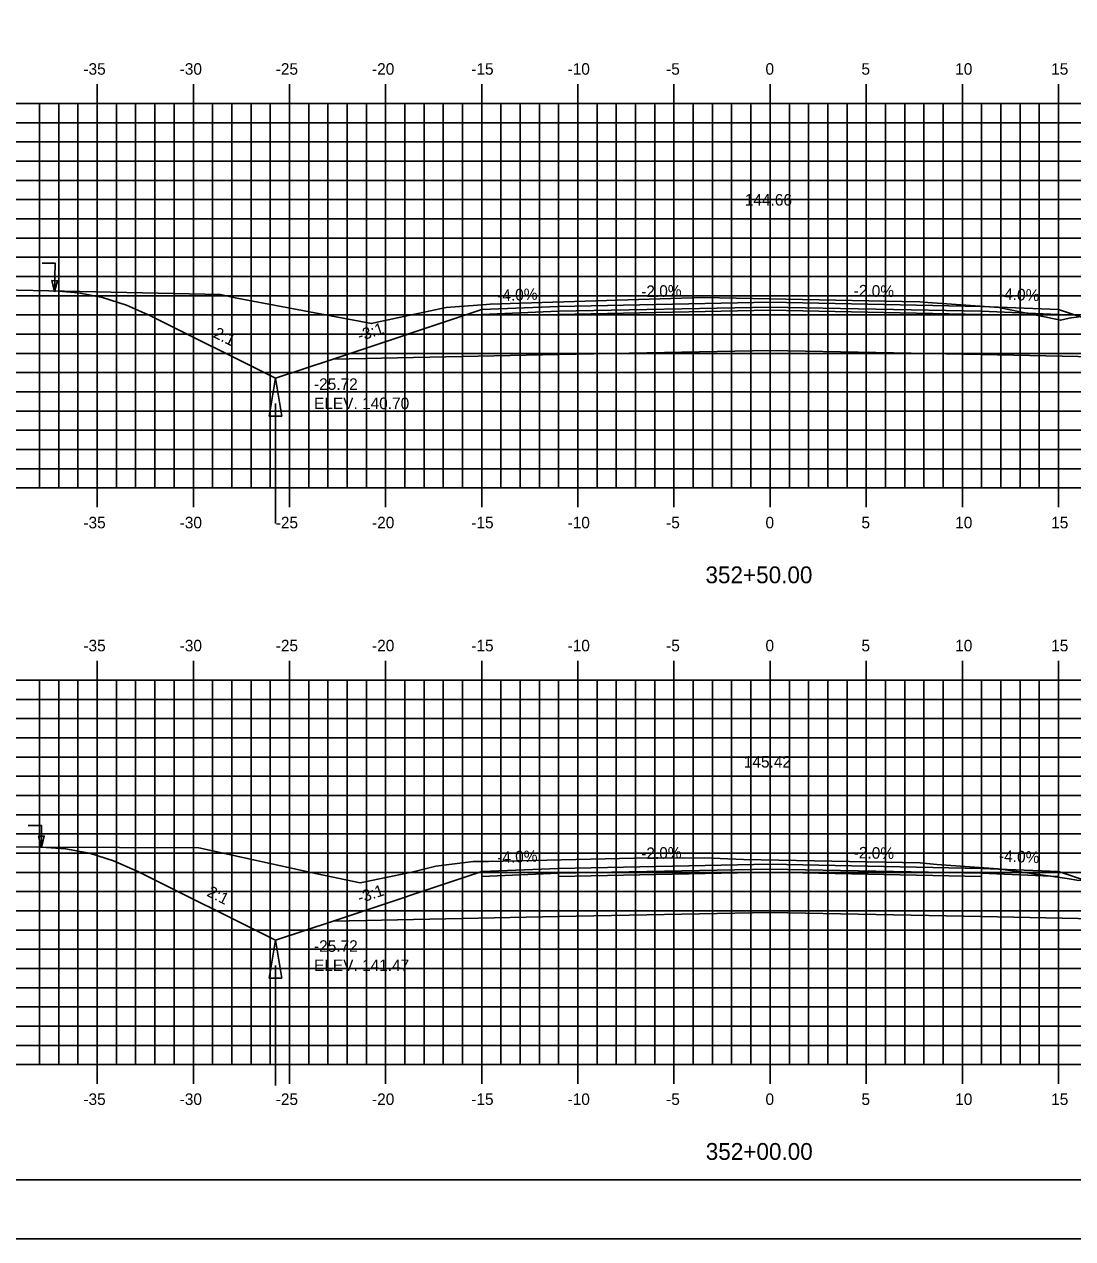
# Model space of a CAD drawing. Extents: x 1144972 to 1145142, y 608981 to 609091.
# Drawn here: x 1145016.6 to 1145071.1, y 608981.3 to 609044.5 of the extents above; entities that cross this region are included whole.
import ezdxf

# ---------------------------------------------------------------- set-up
doc = ezdxf.new("R2010")
doc.units = 0
for name, color, linetype in [('ANNOTATION', 7, 'Continuous'), ('BORDER', 7, 'Continuous'), ('D_Drainage_Ditch_Line', 7, 'Continuous'), ('D_Roadway_Centerline', 7, 'Continuous'), ('D_Roadway_Centerline_Text', 7, 'Continuous'), ('D_Roadway_Edge_Shoulder', 7, 'Continuous'), ('D_Roadway_Edge_TW', 7, 'Continuous'), ('D_Roadway_Pavement', 7, 'Continuous'), ('D_Roadway_SlopeLines', 7, 'Continuous'), ('D_Roadway_SubGrade', 7, 'Continuous'), ('D_Text_Standard', 7, 'Continuous'), ('H_V ANNOTATION', 7, 'Continuous'), ('MAJOR', 7, 'Continuous'), ('MINOR', 7, 'Continuous'), ('PLOT BOUNDARY', 7, 'Continuous'), ('S_Roadway_Centerline', 7, 'Continuous')]:
    doc.layers.add(name, color=color, linetype=linetype)

msp = doc.modelspace()

# ---------------------------------------------------------------- linework, layer by layer
for points in [[(1145018.151, 609030.592), (1145019.401, 609030.491), (1145020.651, 609030.24), (1145021.901, 609029.839), (1145023.151, 609029.289), (1145029.651, 609026.039), (1145032.651, 609027.039), (1145040.374, 609029.614), (1145040.375, 609029.614), (1145044.375, 609029.774), (1145055.375, 609029.994), (1145066.375, 609029.774), (1145070.375, 609029.614), (1145078.099, 609027.039), (1145081.099, 609026.039), (1145086.528, 609028.754), (1145087.778, 609029.302), (1145089.028, 609029.695), (1145090.278, 609029.934), (1145091.528, 609030.018)], [(1145017.48, 609001.649), (1145018.73, 609001.566), (1145019.98, 609001.328), (1145021.23, 609000.935), (1145022.48, 609000.387), (1145029.651, 608996.802), (1145032.651, 608997.802), (1145040.374, 609000.376), (1145040.375, 609000.376), (1145044.375, 609000.536), (1145055.375, 609000.756), (1145066.375, 609000.536), (1145070.375, 609000.376), (1145078.099, 608997.802), (1145081.099, 608996.802), (1145084.992, 608998.748), (1145086.242, 608999.29), (1145087.492, 608999.664), (1145088.742, 608999.87), (1145089.992, 608999.91)]]:
    msp.add_lwpolyline(points)
at = {"layer": 'BORDER'}
msp.add_lwpolyline([(1144980.376, 608984.335), (1145140.376, 608984.335), (1145140.376, 609089.335), (1144980.376, 609089.335)], close=True, dxfattribs=at)
at = {"layer": 'D_Drainage_Ditch_Line'}
for p, q in [((1145029.651, 609024.727), (1145029.65, 609018.483)), ((1145029.651, 608995.489), (1145029.65, 608989.246))]:
    msp.add_line(p, q, dxfattribs=at)
for points in [[(1145029.979, 609024.071), (1145029.323, 609024.071), (1145029.651, 609026.039)], [(1145029.979, 608994.833), (1145029.323, 608994.833), (1145029.651, 608996.802)]]:
    msp.add_lwpolyline(points, close=True, dxfattribs=at)
at = {"layer": 'D_Roadway_Edge_Shoulder'}
for points in [[(1145044.375, 609029.774), (1145040.375, 609029.614), (1145040.375, 609029.364), (1145044.375, 609029.524)], [(1145066.375, 609029.774), (1145070.375, 609029.614), (1145070.375, 609029.364), (1145066.375, 609029.524)], [(1145044.375, 609000.536), (1145040.375, 609000.376), (1145040.375, 609000.126), (1145044.375, 609000.286)], [(1145066.375, 609000.536), (1145070.375, 609000.376), (1145070.375, 609000.126), (1145066.375, 609000.286)]]:
    msp.add_lwpolyline(points, close=True, dxfattribs=at)
at = {"layer": 'D_Roadway_Edge_TW'}
for points in [[(1145044.375, 609029.524), (1145044.375, 609029.774), (1145055.375, 609029.994), (1145066.375, 609029.774), (1145066.375, 609029.524), (1145055.375, 609029.744)], [(1145044.375, 609000.286), (1145044.375, 609000.536), (1145055.375, 609000.756), (1145066.375, 609000.536), (1145066.375, 609000.286), (1145055.375, 609000.506)]]:
    msp.add_lwpolyline(points, close=True, dxfattribs=at)
at = {"layer": 'D_Roadway_Pavement'}
for points in [[(1145044.375, 609029.357), (1145044.375, 609029.524), (1145055.375, 609029.744), (1145066.375, 609029.524), (1145066.375, 609029.357), (1145055.375, 609029.577)], [(1145044.375, 609000.119), (1145044.375, 609000.286), (1145055.375, 609000.506), (1145066.375, 609000.286), (1145066.375, 609000.119), (1145055.375, 609000.339)]]:
    msp.add_lwpolyline(points, close=True, dxfattribs=at)
at = {"layer": 'D_Roadway_SlopeLines'}
for points in [[(1145029.651, 609026.039), (1145023.151, 609029.289), (1145021.901, 609029.839), (1145020.651, 609030.24), (1145019.401, 609030.491), (1145018.151, 609030.592)], [(1145032.651, 609027.039), (1145029.651, 609026.039)], [(1145029.651, 608996.802), (1145022.48, 609000.387), (1145021.23, 609000.935), (1145019.98, 609001.328), (1145018.73, 609001.566), (1145017.48, 609001.649)], [(1145032.651, 608997.802), (1145029.651, 608996.802)]]:
    msp.add_lwpolyline(points, dxfattribs=at)
at = {"layer": 'D_Roadway_SubGrade'}
for points in [[(1145044.375, 609029.357), (1145044.375, 609029.524), (1145040.375, 609029.364), (1145040.375, 609029.614), (1145040.374, 609029.614), (1145032.651, 609027.039), (1145044.375, 609027.274)], [(1145044.375, 609027.274), (1145044.375, 609029.357), (1145055.375, 609029.577), (1145066.375, 609029.357), (1145066.375, 609027.274), (1145055.375, 609027.494)], [(1145066.375, 609029.357), (1145066.375, 609029.524), (1145070.375, 609029.364), (1145070.375, 609029.614), (1145070.376, 609029.614), (1145078.099, 609027.039), (1145066.375, 609027.274)], [(1145044.375, 609000.119), (1145044.375, 609000.286), (1145040.375, 609000.126), (1145040.375, 609000.376), (1145040.374, 609000.376), (1145032.651, 608997.802), (1145044.375, 608998.036)], [(1145044.375, 608998.036), (1145044.375, 609000.119), (1145055.375, 609000.339), (1145066.375, 609000.119), (1145066.375, 608998.036), (1145055.375, 608998.256)], [(1145066.375, 609000.119), (1145066.375, 609000.286), (1145070.375, 609000.126), (1145070.375, 609000.376), (1145070.376, 609000.376), (1145078.099, 608997.802), (1145066.375, 608998.036)]]:
    msp.add_lwpolyline(points, close=True, dxfattribs=at)
at = {"layer": 'D_Text_Standard'}
for points in [[(1145018.151, 609030.539), (1145018.185, 609032.037), (1145017.505, 609032.037)], [(1145017.48, 609001.637), (1145017.469, 609002.782), (1145016.789, 609002.782)]]:
    msp.add_lwpolyline(points, dxfattribs=at)
for points in [[(1145018.151, 609030.539), (1145018.019, 609031.124), (1145018.31, 609031.117)], [(1145017.48, 609001.637), (1145017.329, 609002.218), (1145017.62, 609002.22)]]:
    msp.add_lwpolyline(points, close=True, dxfattribs=at)
at = {"layer": 'MAJOR'}
for p, q in [((1145020.375, 609041.337), (1145020.375, 609040.335)), ((1145025.375, 609041.337), (1145025.375, 609040.335)), ((1145030.375, 609041.337), (1145030.375, 609040.335)), ((1145035.375, 609041.337), (1145035.375, 609040.335)), ((1145040.375, 609041.337), (1145040.375, 609040.335)), ((1145045.375, 609041.337), (1145045.375, 609040.335)), ((1145050.375, 609041.337), (1145050.375, 609040.335)), ((1145055.375, 609041.337), (1145055.375, 609040.335)), ((1145060.375, 609041.337), (1145060.375, 609040.335)), ((1145065.375, 609041.337), (1145065.375, 609040.335)), ((1145070.375, 609041.337), (1145070.375, 609040.335)), ((1144985.375, 609040.335), (1145125.375, 609040.335)), ((1144985.375, 609040.335), (1145125.375, 609040.335)), ((1145020.375, 609020.335), (1145020.375, 609040.335)), ((1145025.375, 609020.335), (1145025.375, 609040.335)), ((1145030.375, 609020.335), (1145030.375, 609040.335)), ((1145035.375, 609020.335), (1145035.375, 609040.335)), ((1145040.375, 609020.335), (1145040.375, 609040.335)), ((1145045.375, 609020.335), (1145045.375, 609040.335)), ((1145050.375, 609020.335), (1145050.375, 609040.335)), ((1145055.375, 609020.335), (1145055.375, 609040.335)), ((1145060.375, 609020.335), (1145060.375, 609040.335)), ((1145065.375, 609020.335), (1145065.375, 609040.335)), ((1145070.375, 609020.335), (1145070.375, 609040.335)), ((1144985.375, 609035.335), (1145125.375, 609035.335)), ((1144985.375, 609030.335), (1145125.375, 609030.335)), ((1144985.375, 609025.335), (1145125.375, 609025.335)), ((1144985.375, 609020.335), (1145125.375, 609020.335)), ((1144985.375, 609020.335), (1145125.375, 609020.335)), ((1145020.375, 609019.333), (1145020.375, 609020.335)), ((1145025.375, 609019.333), (1145025.375, 609020.335)), ((1145030.375, 609019.333), (1145030.375, 609020.335)), ((1145035.375, 609019.333), (1145035.375, 609020.335)), ((1145040.375, 609019.333), (1145040.375, 609020.335)), ((1145045.375, 609019.333), (1145045.375, 609020.335)), ((1145050.375, 609019.333), (1145050.375, 609020.335)), ((1145055.375, 609019.333), (1145055.375, 609020.335)), ((1145060.375, 609019.333), (1145060.375, 609020.335)), ((1145065.375, 609019.333), (1145065.375, 609020.335)), ((1145070.375, 609019.333), (1145070.375, 609020.335)), ((1145020.375, 609011.337), (1145020.375, 609010.335)), ((1145025.375, 609011.337), (1145025.375, 609010.335)), ((1145030.375, 609011.337), (1145030.375, 609010.335)), ((1145035.375, 609011.337), (1145035.375, 609010.335)), ((1145040.375, 609011.337), (1145040.375, 609010.335)), ((1145045.375, 609011.337), (1145045.375, 609010.335)), ((1145050.375, 609011.337), (1145050.375, 609010.335)), ((1145055.375, 609011.337), (1145055.375, 609010.335)), ((1145060.375, 609011.337), (1145060.375, 609010.335)), ((1145065.375, 609011.337), (1145065.375, 609010.335)), ((1145070.375, 609011.337), (1145070.375, 609010.335)), ((1144985.375, 609010.335), (1145125.375, 609010.335)), ((1144985.375, 609010.335), (1145125.375, 609010.335)), ((1145020.375, 608990.335), (1145020.375, 609010.335)), ((1145025.375, 608990.335), (1145025.375, 609010.335)), ((1145030.375, 608990.335), (1145030.375, 609010.335)), ((1145035.375, 608990.335), (1145035.375, 609010.335)), ((1145040.375, 608990.335), (1145040.375, 609010.335)), ((1145045.375, 608990.335), (1145045.375, 609010.335)), ((1145050.375, 608990.335), (1145050.375, 609010.335)), ((1145055.375, 608990.335), (1145055.375, 609010.335)), ((1145060.375, 608990.335), (1145060.375, 609010.335)), ((1145065.375, 608990.335), (1145065.375, 609010.335)), ((1145070.375, 608990.335), (1145070.375, 609010.335)), ((1144985.375, 609005.335), (1145125.375, 609005.335)), ((1144985.375, 609000.335), (1145125.375, 609000.335)), ((1144985.375, 608995.335), (1145125.375, 608995.335)), ((1144985.375, 608990.335), (1145125.375, 608990.335)), ((1144985.375, 608990.335), (1145125.375, 608990.335)), ((1145020.375, 608989.333), (1145020.375, 608990.335)), ((1145025.375, 608989.333), (1145025.375, 608990.335)), ((1145030.375, 608989.333), (1145030.375, 608990.335)), ((1145035.375, 608989.333), (1145035.375, 608990.335)), ((1145040.375, 608989.333), (1145040.375, 608990.335)), ((1145045.375, 608989.333), (1145045.375, 608990.335)), ((1145050.375, 608989.333), (1145050.375, 608990.335)), ((1145055.375, 608989.333), (1145055.375, 608990.335)), ((1145060.375, 608989.333), (1145060.375, 608990.335)), ((1145065.375, 608989.333), (1145065.375, 608990.335)), ((1145070.375, 608989.333), (1145070.375, 608990.335))]:
    msp.add_line(p, q, dxfattribs=at)
at = {"layer": 'MINOR'}
for p, q in [((1145017.375, 609020.335), (1145017.375, 609040.335)), ((1145018.375, 609020.335), (1145018.375, 609040.335)), ((1145019.375, 609020.335), (1145019.375, 609040.335)), ((1145021.375, 609020.335), (1145021.375, 609040.335)), ((1145022.375, 609020.335), (1145022.375, 609040.335)), ((1145023.375, 609020.335), (1145023.375, 609040.335)), ((1145024.375, 609020.335), (1145024.375, 609040.335)), ((1145026.375, 609020.335), (1145026.375, 609040.335)), ((1145027.375, 609020.335), (1145027.375, 609040.335)), ((1145028.375, 609020.335), (1145028.375, 609040.335)), ((1145029.375, 609020.335), (1145029.375, 609040.335)), ((1145031.375, 609020.335), (1145031.375, 609040.335)), ((1145032.375, 609020.335), (1145032.375, 609040.335)), ((1145033.375, 609020.335), (1145033.375, 609040.335)), ((1145034.375, 609020.335), (1145034.375, 609040.335)), ((1145036.375, 609020.335), (1145036.375, 609040.335)), ((1145037.375, 609020.335), (1145037.375, 609040.335)), ((1145038.375, 609020.335), (1145038.375, 609040.335)), ((1145039.375, 609020.335), (1145039.375, 609040.335)), ((1145041.375, 609020.335), (1145041.375, 609040.335)), ((1145042.375, 609020.335), (1145042.375, 609040.335)), ((1145043.375, 609020.335), (1145043.375, 609040.335)), ((1145044.375, 609020.335), (1145044.375, 609040.335)), ((1145046.375, 609020.335), (1145046.375, 609040.335)), ((1145047.375, 609020.335), (1145047.375, 609040.335)), ((1145048.375, 609020.335), (1145048.375, 609040.335)), ((1145049.375, 609020.335), (1145049.375, 609040.335)), ((1145051.375, 609020.335), (1145051.375, 609040.335)), ((1145052.375, 609020.335), (1145052.375, 609040.335)), ((1145053.375, 609020.335), (1145053.375, 609040.335)), ((1145054.375, 609020.335), (1145054.375, 609040.335)), ((1145056.375, 609020.335), (1145056.375, 609040.335)), ((1145057.375, 609020.335), (1145057.375, 609040.335)), ((1145058.375, 609020.335), (1145058.375, 609040.335)), ((1145059.375, 609020.335), (1145059.375, 609040.335)), ((1145061.375, 609020.335), (1145061.375, 609040.335)), ((1145062.375, 609020.335), (1145062.375, 609040.335)), ((1145063.375, 609020.335), (1145063.375, 609040.335)), ((1145064.375, 609020.335), (1145064.375, 609040.335)), ((1145066.375, 609020.335), (1145066.375, 609040.335)), ((1145067.375, 609020.335), (1145067.375, 609040.335)), ((1145068.375, 609020.335), (1145068.375, 609040.335)), ((1145069.375, 609020.335), (1145069.375, 609040.335)), ((1144985.375, 609039.335), (1145125.375, 609039.335)), ((1144985.375, 609038.335), (1145125.375, 609038.335)), ((1144985.375, 609037.335), (1145125.375, 609037.335)), ((1144985.375, 609036.335), (1145125.375, 609036.335)), ((1144985.375, 609034.335), (1145125.375, 609034.335)), ((1144985.375, 609033.335), (1145125.375, 609033.335)), ((1144985.375, 609032.335), (1145125.375, 609032.335)), ((1144985.375, 609031.335), (1145125.375, 609031.335)), ((1144985.375, 609029.335), (1145125.375, 609029.335)), ((1144985.375, 609028.335), (1145125.375, 609028.335)), ((1144985.375, 609027.335), (1145125.375, 609027.335)), ((1144985.375, 609026.335), (1145125.375, 609026.335)), ((1144985.375, 609024.335), (1145125.375, 609024.335)), ((1144985.375, 609023.335), (1145125.375, 609023.335)), ((1144985.375, 609022.335), (1145125.375, 609022.335)), ((1144985.375, 609021.335), (1145125.375, 609021.335)), ((1145017.375, 608990.335), (1145017.375, 609010.335)), ((1145018.375, 608990.335), (1145018.375, 609010.335)), ((1145019.375, 608990.335), (1145019.375, 609010.335)), ((1145021.375, 608990.335), (1145021.375, 609010.335)), ((1145022.375, 608990.335), (1145022.375, 609010.335)), ((1145023.375, 608990.335), (1145023.375, 609010.335)), ((1145024.375, 608990.335), (1145024.375, 609010.335)), ((1145026.375, 608990.335), (1145026.375, 609010.335)), ((1145027.375, 608990.335), (1145027.375, 609010.335)), ((1145028.375, 608990.335), (1145028.375, 609010.335)), ((1145029.375, 608990.335), (1145029.375, 609010.335)), ((1145031.375, 608990.335), (1145031.375, 609010.335)), ((1145032.375, 608990.335), (1145032.375, 609010.335)), ((1145033.375, 608990.335), (1145033.375, 609010.335)), ((1145034.375, 608990.335), (1145034.375, 609010.335)), ((1145036.375, 608990.335), (1145036.375, 609010.335)), ((1145037.375, 608990.335), (1145037.375, 609010.335)), ((1145038.375, 608990.335), (1145038.375, 609010.335)), ((1145039.375, 608990.335), (1145039.375, 609010.335)), ((1145041.375, 608990.335), (1145041.375, 609010.335)), ((1145042.375, 608990.335), (1145042.375, 609010.335)), ((1145043.375, 608990.335), (1145043.375, 609010.335)), ((1145044.375, 608990.335), (1145044.375, 609010.335)), ((1145046.375, 608990.335), (1145046.375, 609010.335)), ((1145047.375, 608990.335), (1145047.375, 609010.335)), ((1145048.375, 608990.335), (1145048.375, 609010.335)), ((1145049.375, 608990.335), (1145049.375, 609010.335)), ((1145051.375, 608990.335), (1145051.375, 609010.335)), ((1145052.375, 608990.335), (1145052.375, 609010.335)), ((1145053.375, 608990.335), (1145053.375, 609010.335)), ((1145054.375, 608990.335), (1145054.375, 609010.335)), ((1145056.375, 608990.335), (1145056.375, 609010.335)), ((1145057.375, 608990.335), (1145057.375, 609010.335)), ((1145058.375, 608990.335), (1145058.375, 609010.335)), ((1145059.375, 608990.335), (1145059.375, 609010.335)), ((1145061.375, 608990.335), (1145061.375, 609010.335)), ((1145062.375, 608990.335), (1145062.375, 609010.335)), ((1145063.375, 608990.335), (1145063.375, 609010.335)), ((1145064.375, 608990.335), (1145064.375, 609010.335)), ((1145066.375, 608990.335), (1145066.375, 609010.335)), ((1145067.375, 608990.335), (1145067.375, 609010.335)), ((1145068.375, 608990.335), (1145068.375, 609010.335)), ((1145069.375, 608990.335), (1145069.375, 609010.335)), ((1144985.375, 609009.335), (1145125.375, 609009.335)), ((1144985.375, 609008.335), (1145125.375, 609008.335)), ((1144985.375, 609007.335), (1145125.375, 609007.335)), ((1144985.375, 609006.335), (1145125.375, 609006.335)), ((1144985.375, 609004.335), (1145125.375, 609004.335)), ((1144985.375, 609003.335), (1145125.375, 609003.335)), ((1144985.375, 609002.335), (1145125.375, 609002.335)), ((1144985.375, 609001.335), (1145125.375, 609001.335)), ((1144985.375, 608999.335), (1145125.375, 608999.335)), ((1144985.375, 608998.335), (1145125.375, 608998.335)), ((1144985.375, 608997.335), (1145125.375, 608997.335)), ((1144985.375, 608996.335), (1145125.375, 608996.335)), ((1144985.375, 608994.335), (1145125.375, 608994.335)), ((1144985.375, 608993.335), (1145125.375, 608993.335)), ((1144985.375, 608992.335), (1145125.375, 608992.335)), ((1144985.375, 608991.335), (1145125.375, 608991.335))]:
    msp.add_line(p, q, dxfattribs=at)
at = {"layer": 'PLOT BOUNDARY'}
msp.add_lwpolyline([(1144972.282, 608981.276), (1145142.282, 608981.276), (1145142.282, 609091.276), (1144972.282, 609091.276)], close=True, dxfattribs=at)
at = {"layer": 'S_Roadway_Centerline'}
for points in [[(1145003.273, 609030.859), (1145005.674, 609030.858), (1145026.787, 609030.408), (1145027.556, 609030.232), (1145034.637, 609028.885), (1145034.944, 609028.954), (1145038.524, 609029.722), (1145040.621, 609029.878), (1145040.81, 609029.897), (1145041.855, 609029.932), (1145051.869, 609030.242), (1145062.239, 609030.04), (1145063.168, 609030.012), (1145063.576, 609029.981), (1145067.267, 609029.729), (1145070.324, 609029.106), (1145070.484, 609029.059), (1145070.938, 609029.17), (1145076.33, 609029.906), (1145081.681, 609029.961), (1145099.892, 609030.068)], [(1145004.115, 609001.735), (1145005.693, 609001.744), (1145009.155, 609001.689), (1145025.656, 609001.61), (1145031.824, 609000.263), (1145034.049, 608999.793), (1145036.738, 609000.354), (1145037.982, 609000.651), (1145039.938, 609000.901), (1145040.734, 609000.893), (1145048.301, 609001.069), (1145051.97, 609001.089), (1145053.987, 609000.998), (1145063.171, 609000.834), (1145064.043, 609000.749), (1145067.23, 609000.521), (1145070.819, 609000.016), (1145071.439, 608999.914), (1145077.139, 609000.29), (1145077.857, 609000.331), (1145083.938, 609000.124), (1145100.699, 608999.529)]]:
    msp.add_lwpolyline(points, dxfattribs=at)

# ---------------------------------------------------------------- texts
at = {"layer": 'ANNOTATION'}
for s, rotation, p in [('-2.0%', 358.85424, (1145059.718, 609030.307)), ('-4.0%', 2.29061, (1145041.191, 609030.047)), ('-2.0%', 1.14576, (1145048.678, 609030.26)), ('-4.0%', 357.70939, (1145067.271, 609030.139)), ('2:1', 333.43495, (1145026.368, 609028.198)), ('-3:1', 18.43482, (1145034.03, 609027.953)), ('-4.0%', 2.29061, (1145041.191, 609000.81)), ('-2.0%', 1.14576, (1145048.678, 609001.022)), ('-2.0%', 358.85424, (1145059.718, 609001.069)), ('-4.0%', 357.70939, (1145067.271, 609000.901)), ('2:1', 333.43495, (1145026.032, 608999.129)), ('-3:1', 18.43482, (1145034.03, 608998.715))]:
    msp.add_text(s, height=0.6, rotation=rotation, dxfattribs=at).set_placement(p)
at = {"layer": 'D_Roadway_Centerline'}
for s, p in [('C', (1145055.37, 609029.994)), ('L', (1145055.375, 609029.986)), ('C', (1145055.37, 609000.756)), ('L', (1145055.375, 609000.749))]:
    msp.add_text(s, height=0.0146, dxfattribs=at).set_placement(p)
at = {"layer": 'D_Roadway_Centerline_Text'}
for s, p in [('144.66', (1145054.059, 609035.026)), ('145.42', (1145054.008, 609005.788))]:
    msp.add_text(s, height=0.6, dxfattribs=at).set_placement(p)
at = {"layer": 'D_Text_Standard'}
for s, p in [('-25.72', (1145031.651, 609025.439)), ('ELEV. 140.70', (1145031.651, 609024.437)), ('-25.72', (1145031.651, 608996.202)), ('ELEV. 141.47', (1145031.651, 608995.2))]:
    msp.add_text(s, height=0.6, dxfattribs=at).set_placement(p)
at = {"layer": 'H_V ANNOTATION'}
for s, height, p in [('-35', 0.6, (1145019.656, 609041.835)), ('-30', 0.6, (1145024.664, 609041.835)), ('-25', 0.6, (1145029.661, 609041.835)), ('-20', 0.6, (1145034.669, 609041.835)), ('-15', 0.6, (1145039.832, 609041.835)), ('-10', 0.6, (1145044.84, 609041.835)), ('-5', 0.6, (1145049.966, 609041.835)), ('0', 0.6, (1145055.135, 609041.835)), ('5', 0.6, (1145060.126, 609041.835)), ('10', 0.6, (1145065.001, 609041.835)), ('15', 0.6, (1145069.993, 609041.835)), ('-35', 0.6, (1145019.656, 609018.235)), ('-30', 0.6, (1145024.664, 609018.235)), ('-25', 0.6, (1145029.661, 609018.235)), ('-20', 0.6, (1145034.669, 609018.235)), ('-15', 0.6, (1145039.832, 609018.235)), ('-10', 0.6, (1145044.84, 609018.235)), ('-5', 0.6, (1145049.966, 609018.235)), ('0', 0.6, (1145055.135, 609018.235)), ('5', 0.6, (1145060.126, 609018.235)), ('10', 0.6, (1145065.001, 609018.235)), ('15', 0.6, (1145069.993, 609018.235)), ('352+50.00', 0.875, (1145052.012, 609015.378)), ('-35', 0.6, (1145019.656, 609011.835)), ('-30', 0.6, (1145024.664, 609011.835)), ('-25', 0.6, (1145029.661, 609011.835)), ('-20', 0.6, (1145034.669, 609011.835)), ('-15', 0.6, (1145039.832, 609011.835)), ('-10', 0.6, (1145044.84, 609011.835)), ('-5', 0.6, (1145049.966, 609011.835)), ('0', 0.6, (1145055.135, 609011.835)), ('5', 0.6, (1145060.126, 609011.835)), ('10', 0.6, (1145065.001, 609011.835)), ('15', 0.6, (1145069.993, 609011.835)), ('-35', 0.6, (1145019.656, 608988.235)), ('-30', 0.6, (1145024.664, 608988.235)), ('-25', 0.6, (1145029.661, 608988.235)), ('-20', 0.6, (1145034.669, 608988.235)), ('-15', 0.6, (1145039.832, 608988.235)), ('-10', 0.6, (1145044.84, 608988.235)), ('-5', 0.6, (1145049.966, 608988.235)), ('0', 0.6, (1145055.135, 608988.235)), ('5', 0.6, (1145060.126, 608988.235)), ('10', 0.6, (1145065.001, 608988.235)), ('15', 0.6, (1145069.993, 608988.235)), ('352+00.00', 0.875, (1145052.028, 608985.378))]:
    msp.add_text(s, height=height, dxfattribs=at).set_placement(p)
at = {"layer": 'S_Roadway_Centerline'}
for s, p in [('L', (1145051.861, 609030.235)), ('C', (1145051.864, 609030.242)), ('L', (1145051.961, 609001.082)), ('C', (1145051.964, 609001.089))]:
    msp.add_text(s, height=0.0146, dxfattribs=at).set_placement(p)

doc.saveas('drawing.dxf')
